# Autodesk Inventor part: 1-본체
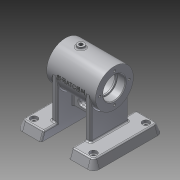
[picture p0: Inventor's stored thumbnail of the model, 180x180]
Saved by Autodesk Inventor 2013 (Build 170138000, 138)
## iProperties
Created: 2016-07
Part Number: 1-본체
Material: 알루미늄 6061
Document SubType Name: Modeling
Designer: WINDOWS7
Density: 2.71 g/cm^3
Mass: 500.251 g
Surface Area: 539.955 cm^2
Volume: 184.594 cm^3
Author: WINDOWS7
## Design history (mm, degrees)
sketch "스케치1"
  geometry: C1 r 27 at (0, 0); 1 further point
  constraints: 1 centre point, 1 coincident
  dimensions: "d0" = 54 diameter of C1
extrude "돌출1" new body sketch "스케치1" stored distance "d1" = 70; taper "d2" = 0 deg
node "작업 평면1"
sketch "스케치3"
  geometry: L1 (-50, -70)-(50, -70); L2 (50, -70)-(45.632, -58); L3 (45.632, -58)-(-45.632, -58); L4 (-45.632, -58)-(-50, -70); 2 further points
  constraints: 8 end point, 1 horizontal, 1 midpoint, 1 parallel, 1 vertical alignment
  dimensions: "d7" = 70 deg angle of L1 L4; "d8" = 70 deg angle of L1 L2; "d9" = 12 distance between parallel lines of L1 L3; "d11" = 70 distance from line of L1 point (0, 0); "d12" = 100 distance of L1.start L1.end
extrude "돌출2" join sketch "스케치3" distance "d13" = 35; taper "d14" = 0 deg
sketch "스케치5"
  geometry: L1 (-55, -58)-(-55, -70) reference; L2 (-55, -58)-(-20, -58) reference; L3 (-55, -70)-(-20, -70) reference; L4 (-55, -58)-(-55, -70); L5 (-55, -70)-(-50.632, -58); L6 (-50.632, -58)-(-55, -58); 1 further point
  constraints: 6 end point, 1 collinear, 1 perpendicular, 1 point on line
  dimensions: "d16" = 70 deg angle of L5 L6
extrude "돌출3" cut sketch "스케치5" stored distance "d17" = 35; taper "d18" = 0 deg
sketch "스케치6"
  geometry: L1 (0, 27)-(-64.229, 27); L2 (-64.229, 27)-(-64.229, -27); L3 (-64.229, -27)-(0, -27); L4 (0, -27)-(0, 27); C1 r 27 at (0, 0) reference; 2 further points
  constraints: 8 end point, 2 coincident, 2 parallel, 1 horizontal, 1 midpoint, 1 perpendicular
  dimensions: "d19" = 54 distance of L1.end L2.end
extrude "돌출4" join sketch "스케치6" distance "d21" = 8; taper "d22" = 0 deg
sketch "스케치7"
  geometry: 5 further points
  constraints: 2 horizontal alignment, 2 vertical alignment
  dimensions: "d23" = 85 distance of point (22.5, 83.132) point (-62.5, 83.132); "d25" = 75 distance of point (-62.5, 8.132) point (-62.5, 83.132); "d26" = 37.5 vertical distance of point (-20, 45.632) point (-62.5, 8.132); "d27" = 42.5 horizontal distance of point (-20, 45.632) point (22.5, 83.132)
hole "구멍1" sketch "스케치7" at (22.5, 83.132), (-62.5, 83.132), (-62.5, 8.132), (22.5, 8.132) diameter "d28" = 6; stored, may be unused: countersink angle "d32" = 90 deg, drill point angle "d34" = 118 deg; dims "d29" = 6, "d30" = 10, "d31" = 4, "d33" = 8
node "작업 평면2"
node "작업 평면3"
sketch "스케치8"
  geometry: L1 (-55, 77)-(-55, 23) reference; C1 r 5 at (-33, 50); 1 further point
  constraints: 1 centre point, 1 horizontal alignment
  dimensions: "d36" = 22 distance from line of L1 C1.centre; "d37" = 10 diameter of C1
extrude "돌출5" join sketch "스케치8" distance "d38" = 8; taper "d39" = 0 deg
sketch "스케치9"
  geometry: L1 (-20, -48)-(20, -48); L2 (-20, -58)-(-20, 0) reference; L3 (20, -58)-(20, 0) reference; L4 (35, -27)-(-35, -27) reference; L5 (-20, -20.108)-(20, -20.108); L6 (-20, -48)-(-20, -20.108); L7 (20, -48)-(20, -20.108); L8 (-8, -34.5)-(8, -34.5); L9 (8, -41.5)-(-8, -41.5); L10 (55, -70)-(20, -70) reference; A1 r 3.5 centre (-8, -38) between (-8, -34.5) and (-8, -41.5); A2 r 3.5 centre (8, -38) between (8, -41.5) and (8, -34.5); 3 further points
  constraints: 12 end point, 4 point on circle, 3 parallel, 3 tangent, 2 centre point, 2 collinear, 2 midpoint, 2 point on line, 1 vertical alignment
  dimensions: "d41" = 21 distance between parallel lines of L1 L4; "d42" = 7 diameter of A1; "d43" = 7 diameter of A2; "d44" = 32 distance from line of A2.centre L10; "d45" = 23 dimension on A2 A1
extrude "돌출6" join sketch "스케치9" stored distance "d46" = 8; taper "d47" = 0 deg
sketch "스케치10"
  geometry: L1 (35, 0)-(-35, 0); L2 (-35, 0)-(-35, 16); L3 (-35, 16)-(-23, 16); L4 (-23, 16)-(-23, 14); L5 (-23, 14)-(-21, 14); L6 (-21, 14)-(-21, 22); L7 (-21, 22)-(21, 22); L8 (21, 22)-(21, 14); L9 (21, 14)-(23, 14); L10 (23, 14)-(23, 16); L11 (23, 16)-(35, 16); L12 (35, 16)-(35, 0); L13 (35, -27)-(35, 27) reference; L14 (-35, 27)-(-35, -27) reference; 2 further points
  constraints: 24 end point, 10 parallel, 2 collinear, 1 coincident, 1 horizontal, 1 midpoint, 1 perpendicular
  dimensions: "d48" = 32 diameter of L3 L1; "d50" = 28 diameter of L5 L1; "d51" = 12 distance of L2.end L3.end; "d52" = 42 distance of L6.end L7.end; "d53" = 2 distance of L4.end L5.end; "d54" = 12 distance of L10.end L11.end; "d55" = 2 distance of L8.end L9.end (derived); "d56" = 32 diameter of L11 L1; "d57" = 28 diameter of L9 L1; "d58" = 44 diameter of L7 L1
revolve "회전1" sketch "스케치10" stored, may be unused: angle "d59" = 90 deg
hole "구멍2" diameter "d62" = 5.188; stored, may be unused: countersink angle "d66" = 90 deg, drill point angle "d68" = 118 deg; dims "d63" = 6, "d64" = 10, "d65" = 4, "d67" = 20, "d69" = 10, "d70" = 10
sketch "스케치11"
  geometry: C1 r 16 at (0, 0) reference; 1 further point
  constraints: 1 horizontal alignment
  dimensions: "d71" = 21 distance of C1.centre point (-21, 0)
hole "구멍3" sketch "스케치11" at (-21, 0) diameter "d72" = 3.242; stored, may be unused: countersink angle "d76" = 90 deg, drill point angle "d78" = 118 deg; dims "d73" = 8, "d74" = 10, "d75" = 4, "d77" = 10
node "작업 평면6"
  node "작업 평면5"
sketch "스케치12"
  geometry: C1 r 6 at (0, 0); 1 further point
  constraints: 1 centre point, 1 coincident
  dimensions: "d84" = 12 diameter of C1
extrude "돌출7" join sketch "스케치12" distance "d85" = 5; taper "d86" = 0 deg
hole "구멍4" diameter "d89" = 5.188; stored, may be unused: countersink angle "d93" = 90 deg, drill point angle "d95" = 118 deg; dims "d87" = 10, "d88" = 10, "d90" = 8, "d91" = 10, "d92" = 4, "d94" = 15
fillet "모깎기1" dims "d96" = 0.3
fillet "모깎기2" dims "d97" = 10, "d98" = 5
fillet "모깎기3" dims "d99" = 5, "d100" = 10
fillet "모깎기4" dims "d101" = 3
chamfer "모따기1" distance "d102" = 1; stored, may be unused: second distance "d103" = 2, angle "d104" = 45 deg
fillet "모깎기5" dims "d105" = 2
fillet "모깎기6" dims "d106" = 2
fillet "모깎기7" dims "d107" = 2
fillet "모깎기8" dims "d108" = 2
fillet "모깎기9" dims "d109" = 2
fillet "모깎기10" dims "d110" = 2
fillet "모깎기11" dims "d111" = 2
fillet "모깎기12" dims "d112" = 2
fillet "모깎기13" dims "d113" = 2
fillet "모깎기14" dims "d114" = 2
node "작업 평면7"
sketch "스케치13"
  geometry: L1 (-20.739, 3.002)-(20.739, 3.002); L2 (20.739, 3.002)-(20.739, -3.002); L3 (20.739, -3.002)-(-20.739, -3.002); L4 (-20.739, -3.002)-(-20.739, 3.002); L5 (-20.739, 0)-(20.739, 0); L6 (0, 3.002)-(0, -3.002); L7 (-35, 27)-(35, 27) reference; 2 further points
  constraints: 5 midpoint, 4 end point, 1 coincident, 2 other
  dimensions: "d115" = 27 distance from line of point (0, 0) L7
feature "엠보싱1" sketch "스케치13" dims "d16" = 70 deg, "d116" = 0.5, "d117" = 0
node "솔리드1"
mirror "대칭1"
mirror "대칭2"
pattern_circular "원형 패턴1" dims angle "d80" = 360 deg
mirror "대칭3"
mirror "대칭4"
node "작업 평면4"
other parameters: "d3" = 55, "d82" = 58 deg, "d83" = 3
